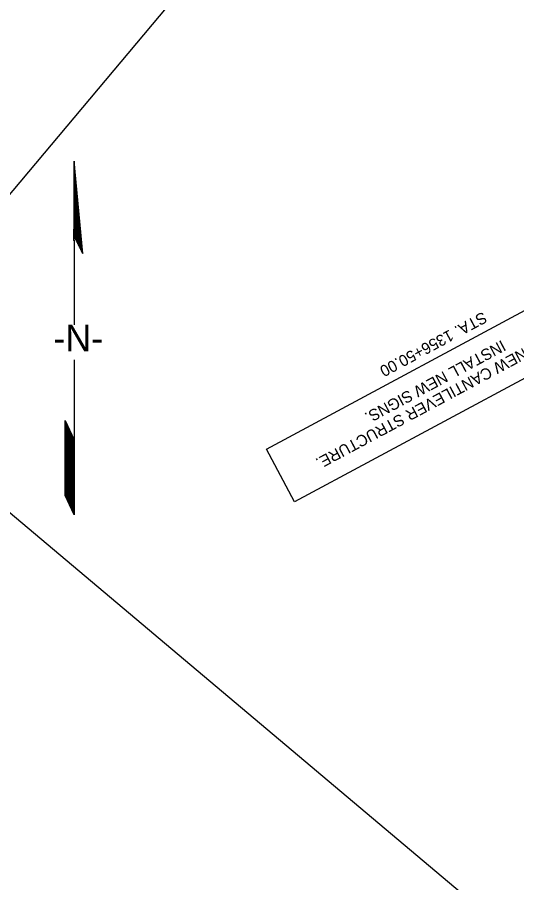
# Model space of a CAD drawing. Extents: x 2001876 to 2025694, y 804561 to 868938.
# Drawn here: x 2011719 to 2012600, y 821154 to 822680 of the extents above; entities that cross this region are included whole.
import ezdxf

# ---------------------------------------------------------------- set-up
doc = ezdxf.new("R2010")
doc.units = 0
for name, color, linetype in [('North Arrow', 7, 'Continuous'), ('RD_SHT_ShtClip', 7, 'Continuous'), ('TR SN EXTRUDED PANEL SIGNS- MOUNTED OVERHEAD', 7, 'Continuous')]:
    doc.layers.add(name, color=color, linetype=linetype)

msp = doc.modelspace()

# ---------------------------------------------------------------- linework, layer by layer
at = {"layer": 'North Arrow'}
for p, q in [((2011819.9, 822426.2), (2011819, 822285.5)), ((2011834.8, 822263.4), (2011819.9, 822426.2)), ((2011819.9, 822286.7), (2011819.9, 822199.4)), ((2011821.1, 822291.1), (2011834.8, 822263.4)), ((2011819.9, 822199.4), (2011819.9, 822137.5)), ((2011819.9, 822075.7), (2011819.9, 821972.6)), ((2011803.9, 821912.4), (2011803.9, 821969.1)), ((2011803.9, 821969.1), (2011819.9, 821934.8)), ((2011819.9, 821972.6), (2011819.9, 821802.6)), ((2011803.9, 821836.8), (2011803.9, 821912.4)), ((2011819.9, 821802.6), (2011803.9, 821836.8))]:
    msp.add_line(p, q, dxfattribs=at)
for points in [[(2011819.9, 822287.9), (2011819.9, 822425.7)], [(2011820.3, 822289), (2011820.3, 822421.6)], [(2011820.7, 822290), (2011820.7, 822417.4)], [(2011821.1, 822291), (2011821.1, 822413.3)], [(2011821.4, 822290.4), (2011821.4, 822409.2)], [(2011821.8, 822289.7), (2011821.8, 822405)], [(2011822.2, 822288.9), (2011822.2, 822400.9)], [(2011822.6, 822288.1), (2011822.6, 822396.8)], [(2011822.9, 822287.4), (2011822.9, 822392.7)], [(2011823.3, 822286.6), (2011823.3, 822388.5)], [(2011823.7, 822285.8), (2011823.7, 822384.4)], [(2011824.1, 822285.1), (2011824.1, 822380.3)], [(2011824.5, 822284.3), (2011824.5, 822376.1)], [(2011819.5, 822286.9), (2011819.5, 822370)], [(2011824.8, 822283.5), (2011824.8, 822372)], [(2011825.2, 822282.8), (2011825.2, 822367.9)], [(2011825.6, 822282), (2011825.6, 822363.7)], [(2011826, 822281.2), (2011826, 822359.6)], [(2011826.3, 822280.5), (2011826.3, 822355.5)], [(2011826.7, 822279.7), (2011826.7, 822351.4)], [(2011827.1, 822278.9), (2011827.1, 822347.2)], [(2011827.5, 822278.2), (2011827.5, 822343.1)], [(2011827.9, 822277.4), (2011827.9, 822339)], [(2011828.2, 822276.6), (2011828.2, 822334.8)], [(2011828.6, 822275.9), (2011828.6, 822330.7)], [(2011829, 822275.1), (2011829, 822326.6)], [(2011829.4, 822274.3), (2011829.4, 822322.4)], [(2011829.8, 822273.6), (2011829.8, 822318.3)], [(2011830.1, 822272.8), (2011830.1, 822314.2)], [(2011819.2, 822285.9), (2011819.2, 822306.4)], [(2011830.5, 822272), (2011830.5, 822310.1)], [(2011830.9, 822271.3), (2011830.9, 822305.9)], [(2011831.3, 822270.5), (2011831.3, 822301.8)], [(2011831.6, 822269.7), (2011831.6, 822297.7)], [(2011832, 822269), (2011832, 822293.5)], [(2011832.4, 822268.2), (2011832.4, 822289.4)], [(2011832.8, 822267.4), (2011832.8, 822285.3)], [(2011833.2, 822266.7), (2011833.2, 822281.1)], [(2011833.5, 822265.9), (2011833.5, 822277)], [(2011833.9, 822265.1), (2011833.9, 822272.9)], [(2011834.3, 822264.4), (2011834.3, 822268.8)], [(2011834.7, 822263.6), (2011834.7, 822264.6)], [(2011804.2, 821836.2), (2011804.2, 821968.4)], [(2011804.6, 821835.3), (2011804.6, 821967.6)], [(2011805, 821834.5), (2011805, 821966.8)], [(2011805.3, 821833.7), (2011805.3, 821966)], [(2011805.7, 821832.9), (2011805.7, 821965.2)], [(2011806.1, 821832.1), (2011806.1, 821964.4)], [(2011806.5, 821831.3), (2011806.5, 821963.6)], [(2011806.9, 821830.5), (2011806.9, 821962.8)], [(2011807.2, 821829.7), (2011807.2, 821961.9)], [(2011807.6, 821828.9), (2011807.6, 821961.1)], [(2011808, 821828), (2011808, 821960.3)], [(2011808.4, 821827.2), (2011808.4, 821959.5)], [(2011808.7, 821826.4), (2011808.7, 821958.7)], [(2011809.1, 821825.6), (2011809.1, 821957.9)], [(2011809.5, 821824.8), (2011809.5, 821957.1)], [(2011809.9, 821824), (2011809.9, 821956.3)], [(2011810.3, 821823.2), (2011810.3, 821955.5)], [(2011810.6, 821822.4), (2011810.6, 821954.7)], [(2011811, 821821.6), (2011811, 821953.8)], [(2011811.4, 821820.8), (2011811.4, 821953)], [(2011811.8, 821819.9), (2011811.8, 821952.2)], [(2011812.2, 821819.1), (2011812.2, 821951.4)], [(2011812.5, 821818.3), (2011812.5, 821950.6)], [(2011812.9, 821817.5), (2011812.9, 821949.8)], [(2011813.3, 821816.7), (2011813.3, 821949)], [(2011813.7, 821815.9), (2011813.7, 821948.2)], [(2011814, 821815.1), (2011814, 821947.4)], [(2011814.4, 821814.3), (2011814.4, 821946.5)], [(2011814.8, 821813.5), (2011814.8, 821945.7)], [(2011815.2, 821812.6), (2011815.2, 821944.9)], [(2011815.6, 821811.8), (2011815.6, 821944.1)], [(2011815.9, 821811), (2011815.9, 821943.3)], [(2011816.3, 821810.2), (2011816.3, 821942.5)], [(2011816.7, 821809.4), (2011816.7, 821941.7)], [(2011817.1, 821808.6), (2011817.1, 821940.9)], [(2011817.4, 821807.8), (2011817.4, 821940.1)], [(2011817.8, 821807), (2011817.8, 821939.3)], [(2011818.2, 821806.2), (2011818.2, 821938.4)], [(2011818.6, 821805.4), (2011818.6, 821937.6)], [(2011819, 821804.5), (2011819, 821936.8)], [(2011819.3, 821803.7), (2011819.3, 821936)], [(2011819.7, 821802.9), (2011819.7, 821935.2)]]:
    msp.add_lwpolyline(points, dxfattribs=at)
at = {"layer": 'RD_SHT_ShtClip'}
for p, q in [((2011429.3, 822038.4), (2012671.5, 823516.1)), ((2016066.1, 818140.6), (2011429.3, 822038.4))]:
    msp.add_line(p, q, dxfattribs=at)
at = {"layer": 'TR SN EXTRUDED PANEL SIGNS- MOUNTED OVERHEAD'}
msp.add_lwpolyline([(2012751.7, 822117), (2012208.4, 821825.7), (2012158.7, 821918.5), (2012701.9, 822209.8)], close=True, dxfattribs=at)

# ---------------------------------------------------------------- texts
at = {"layer": 'North Arrow'}
msp.add_text('-N-', height=47.24, rotation=0, dxfattribs=at).set_placement((2011783.1, 822090.6))
at = {"layer": 'TR SN EXTRUDED PANEL SIGNS- MOUNTED OVERHEAD'}
for s, p in [('STA. 1356+50.00', (2012540.9, 822161.3)), ('ERECT NEW CANTILEVER STRUCTURE.', (2012698.1, 822143.9)), ('INSTALL NEW SIGNS.', (2012573.8, 822111.3))]:
    msp.add_text(s, height=20, rotation=208.2027, dxfattribs=at).set_placement(p)

doc.saveas('drawing.dxf')
